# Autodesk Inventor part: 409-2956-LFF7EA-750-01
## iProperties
Created: 2010-06
Part Number: 409-2956-LFF7EA-750-01
Material: Sch40 CS PIPE SEAMLESS
Description: PIPE
Document SubType Name: Modeling
Designer: S. Boerckel
Engineer: Steve Boerckel
Mass: 2488.07 g
Surface Area: 1634.44 cm^2
Volume: 316.951 cm^3
Density: 7.85 g/cm^3
Cost Center: 4"
SMR: =<COST CENTER> - <Material>
Length: 18.000 in
Title: 2"
Author: S. Boerckel
Revision Number: B
Subject: DEMIN WATER FORWARDING PUMP SKID-7EA
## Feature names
1. Extrusion1
